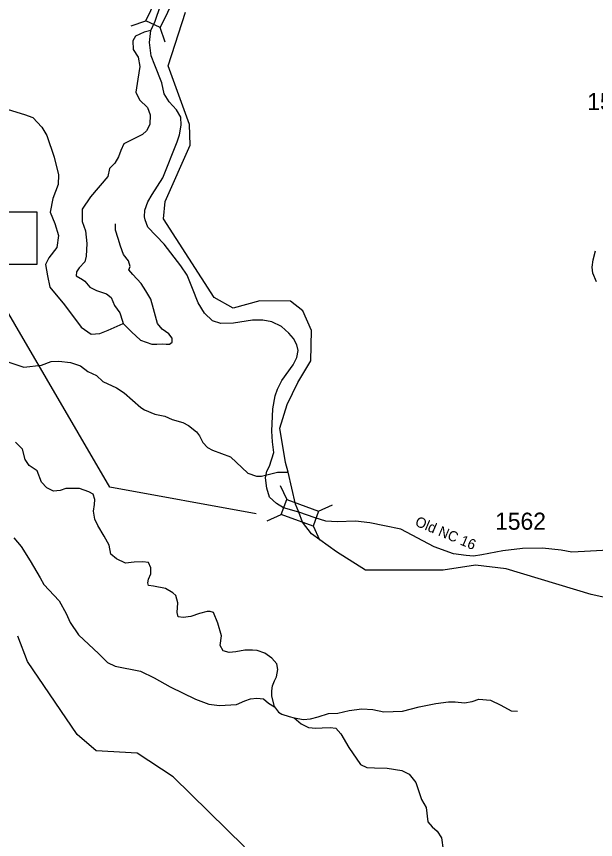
# Model space of a CAD drawing. Extents: x 1248224 to 1454986, y 825081 to 985870.
# Drawn here: x 1314642 to 1318874, y 928409 to 934427 of the extents above; entities that cross this region are included whole.
import ezdxf

# ---------------------------------------------------------------- set-up
doc = ezdxf.new("R2010")
doc.units = 0
for name, color, linetype in [('Exist Hydrographic Creek Single Shore', 7, 'Continuous'), ('Exist Hydrographic Misc Water Feature', 7, 'Continuous'), ('Exist Road Non-System Type 51', 7, 'Continuous'), ('Exist Road Secondary Structure Standard Bridge CELL', 7, 'Continuous'), ('Exist Road Secondary Structure Standard Bridge Number Label', 7, 'Continuous'), ('Exist Road Secondary Type 10 Attributed', 7, 'Continuous'), ('Exist Road Secondary Type 51 Attributed', 7, 'Continuous'), ('Exist Road Secondary Type 51 Label', 7, 'Continuous'), ('Exist Road Secondary Type 51 Number Label', 7, 'Continuous')]:
    doc.layers.add(name, color=color, linetype=linetype)

msp = doc.modelspace()

# ---------------------------------------------------------------- linework, layer by layer
at = {"layer": 'Exist Hydrographic Creek Single Shore'}
for points in [[(1316706.6, 930803.7), (1316682.2, 930860.1), (1316628.6, 931094.5), (1316608, 931166.9), (1316566.6, 931417.7), (1316620.9, 931591), (1316698.4, 931751.3), (1316792.5, 931908.1), (1316797.5, 932131.2), (1316734.5, 932273.6), (1316644.5, 932344.3), (1316419.5, 932348.9), (1316226.5, 932293.7), (1316086.5, 932372), (1315716.5, 932947.4), (1315727.5, 933075.2), (1315911.5, 933485.2), (1315907.5, 933636.2), (1315750.4, 934066.1), (1315878, 934458.4)], [(1316798.9, 930644.8), (1316732.9, 930729.2), (1316706.6, 930803.7)], [(1319185.3, 930124.2), (1318842.9, 930199.8), (1318220.7, 930388.5), (1317995.7, 930416.1), (1317761.4, 930379.3), (1317191.9, 930379.3), (1316980.6, 930512.7), (1316798.9, 930644.8)]]:
    msp.add_lwpolyline(points, dxfattribs=at)
at = {"layer": 'Exist Hydrographic Misc Water Feature'}
for points in [[(1314572, 931904.8), (1314695.1, 931862.1), (1314823.6, 931876.7), (1314896.1, 931903.2), (1314952.2, 931907.8), (1315036.2, 931897.9), (1315109.6, 931871.8), (1315162.7, 931830.6), (1315226, 931801.4), (1315273, 931758.6), (1315374, 931712.3), (1315429.3, 931675), (1315550.9, 931567.5), (1315578.5, 931551.4), (1315653.8, 931519.5), (1315725.6, 931505.8), (1315780.9, 931480), (1315858.5, 931458.8), (1315898, 931435.8), (1315957, 931390.3), (1315980.4, 931361.9), (1316003.2, 931313), (1316038.4, 931276.2), (1316074, 931255), (1316206.9, 931208), (1316332.2, 931087.4), (1316395.8, 931065.5), (1316431.8, 931064.8), (1316548.6, 931096.1), (1316628.6, 931094.5)], [(1316309.5, 928355.8), (1315787.5, 928868.5), (1315524.5, 929041.2), (1315224.5, 929057.1), (1315086.5, 929178), (1314723.4, 929710.6), (1314652.5, 929895.9)]]:
    msp.add_lwpolyline(points, dxfattribs=at)
at = {"layer": 'Exist Road Non-System Type 51'}
for points in [[(1315624.6, 934325.9), (1315575.2, 934313.3), (1315511.5, 934282.4), (1315493.1, 934249.5), (1315495.1, 934185.8), (1315532.1, 934130.3), (1315542.3, 934060.4), (1315528, 933970), (1315513.6, 933873.4), (1315540.3, 933817.9), (1315599.9, 933762.4), (1315618.3, 933706.9), (1315616.3, 933637), (1315591.6, 933591.8), (1315562.9, 933565.1), (1315427.3, 933495.2), (1315404.9, 933447.4), (1315388.4, 933400.1), (1315359.7, 933354.9), (1315322.7, 933315.9), (1315310.4, 933258.3), (1315183.1, 933108.3), (1315121.4, 933017.8), (1315121.4, 932927.4), (1315146.1, 932859.6), (1315156.4, 932767.1), (1315150.2, 932674.6), (1315142.1, 932634.3), (1315101, 932589.1), (1315080.5, 932560.3), (1315078.4, 932531.6), (1315125.6, 932504.8), (1315142.1, 932492.5), (1315177, 932447.3), (1315226.3, 932424.7), (1315300.2, 932398), (1315335.1, 932373.3), (1315357.7, 932313.7), (1315396.8, 932260.2), (1315417.3, 932198.6), (1315421.4, 932182.1)], [(1314581.2, 933746.1), (1314699.4, 933710.2), (1314760.3, 933688.7), (1314828.4, 933617), (1314864.2, 933556.1), (1314917.9, 933398.4), (1314950.2, 933269.3), (1314946.6, 933197.6), (1314907.2, 933097.2), (1314889.3, 932996.9), (1314921.5, 932914.4), (1314950.2, 932824.8), (1314935.8, 932738.8), (1314878.5, 932663.5), (1314853.5, 932613.3), (1314867.8, 932530.9), (1314885.7, 932448.4), (1314993.2, 932319.4), (1315114.9, 932154.5), (1315186.6, 932104.3), (1315251.1, 932107.9), (1315311.9, 932133), (1315421.4, 932182.1)], [(1315421.4, 932182.1), (1315483, 932120.5), (1315548.7, 932060.9), (1315630.9, 932032.1), (1315667.9, 932032.1), (1315708.9, 932034.2), (1315735.6, 932030), (1315761.4, 932030.9), (1315779.9, 932045.3), (1315779.9, 932076.1), (1315755.2, 932107), (1315705.9, 932139.8), (1315673.1, 932181), (1315644.3, 932289.9), (1315623.8, 932359.8), (1315586.8, 932421.4), (1315553.9, 932474.9), (1315492.8, 932541.6), (1315464.1, 932574.5), (1315472.3, 932599.2), (1315460, 932640.3), (1315423, 932687.5), (1315402.5, 932747.1), (1315386, 932804.7), (1315365.5, 932864.3), (1315365.5, 932911.6)], [(1316527.5, 929379.5), (1316509, 929459.6), (1316509, 929496.6), (1316513.1, 929531.6), (1316527.5, 929568.6), (1316541.9, 929599.4), (1316552.1, 929652.8), (1316543.9, 929693.9), (1316509, 929735), (1316457.6, 929772), (1316402.2, 929790.5), (1316367.3, 929794.6), (1316309.8, 929792.6), (1316246.1, 929780.3), (1316196.8, 929776.1), (1316153.7, 929788.5), (1316131.1, 929827.5), (1316139.3, 929897.4), (1316114.7, 929989.9), (1316081.8, 930070.1), (1316057.1, 930076.2), (1316034.6, 930076.2), (1315979.1, 930061.8), (1315915.4, 930039.2), (1315860, 930033.1), (1315823, 930037.2), (1315816.8, 930070.1), (1315821, 930139.9), (1315806.6, 930193.4), (1315784, 930213.9), (1315730.6, 930244.8), (1315642.9, 930262.3), (1315608, 930266.4), (1315601.8, 930287), (1315608, 930313.7), (1315624.4, 930352.8), (1315624.4, 930395.9), (1315608, 930435), (1315564.9, 930439.1), (1315501.2, 930437), (1315439.6, 930430.9), (1315371.8, 930461.7), (1315330.7, 930494.6), (1315320.5, 930560.4), (1315283.5, 930626.1), (1315236.2, 930706.3), (1315213.6, 930751.5), (1315205.5, 930810.1), (1315211.7, 930859.4), (1315213.8, 930894.3), (1315203.5, 930933.4), (1315170.6, 930951.9), (1315102.9, 930974.5), (1315002.2, 930974.5), (1314961.1, 930962.2), (1314911.8, 930956), (1314864.6, 930980.7), (1314825.6, 931021.8), (1314792.7, 931106), (1314735.2, 931143), (1314706.5, 931188.3), (1314685.9, 931264.3), (1314634.6, 931313.6)], [(1314623.2, 930615.6), (1314676.6, 930551.9), (1314742.3, 930447.1), (1314814.2, 930321.7), (1314843, 930274.4), (1314953.9, 930153.1), (1315005.2, 930062.7), (1315034, 929994.9), (1315095.6, 929906.5), (1315244.8, 929767.7), (1315306.4, 929704), (1315363.9, 929677.3), (1315548.7, 929640.3), (1315649.4, 929591), (1315764.4, 929525.2), (1315951.3, 929434.8), (1316047.8, 929397.8), (1316125.9, 929389.5), (1316249.1, 929395.7), (1316309.8, 929422.6), (1316352.9, 929437), (1316398.1, 929443.2), (1316447.4, 929437), (1316484.3, 929406.2), (1316527.5, 929379.5)], [(1316670.7, 929299.9), (1316740.5, 929285.5), (1316791.9, 929291.7), (1316847.3, 929306.1), (1316921.3, 929330.7), (1316991.1, 929332.8), (1317073.3, 929353.4), (1317165.7, 929363.6), (1317245.8, 929359.5), (1317327.9, 929343.1), (1317463.5, 929347.2), (1317584.7, 929378), (1317705.8, 929404.7), (1317798.3, 929415), (1317847.6, 929415), (1317916.4, 929408.9), (1317971.9, 929417.1), (1318021.2, 929435.6), (1318105.4, 929427.4), (1318181.4, 929392.4), (1318257.4, 929349.3), (1318304.6, 929347.2)], [(1316527.5, 929379.5), (1316557.7, 929341), (1316580.3, 929324.6), (1316633.7, 929308.1), (1316670.7, 929299.9)], [(1316670.7, 929299.9), (1316723.3, 929255.4), (1316776.7, 929228.7), (1316830.1, 929222.6), (1316877.3, 929226.7), (1316934.8, 929228.7), (1316975.9, 929222.6), (1317012.9, 929181.4), (1317070.4, 929082.8), (1317156.7, 928957.4), (1317201.8, 928934.8), (1317259.3, 928932.7), (1317351.8, 928930.7), (1317458.6, 928914.2), (1317512, 928887.5), (1317561.3, 928825.9), (1317602.3, 928700.5), (1317635.2, 928642.9), (1317647.5, 928538.1), (1317680.4, 928501.1), (1317717.4, 928470.3), (1317748.2, 928421), (1317760.5, 928332.6)]]:
    msp.add_lwpolyline(points, dxfattribs=at)
at = {"layer": 'Exist Road Secondary Structure Standard Bridge CELL'}
for p, q in [((1315481.1, 934358.9), (1315587.9, 934396.3)), ((1315729.7, 934239.3), (1315692.3, 934346.1)), ((1316569.1, 930998.1), (1316616.7, 930895.4)), ((1316849.2, 930809.4), (1316951.9, 930856.9)), ((1316474, 930739.2), (1316576.7, 930786.7)), ((1316810.1, 930703.2), (1316857.7, 930600.5))]:
    msp.add_line(p, q, dxfattribs=at)
for points in [[(1315587.9, 934396.3), (1315695.4, 934619.7), (1315799.8, 934569.5), (1315692.3, 934346.1)], [(1316616.7, 930895.4), (1316849.3, 930809.9), (1316809.4, 930701.2), (1316576.7, 930786.7)]]:
    msp.add_lwpolyline(points, close=True, dxfattribs=at)
at = {"layer": 'Exist Road Secondary Structure Standard Bridge Number Label'}
msp.add_lwpolyline([(1313861.3, 932997.9), (1314790.2, 932997.9), (1314790.2, 932613.8), (1313861.3, 932613.8)], close=True, dxfattribs=at)
msp.add_lwpolyline([(1316394.7, 930790.4), (1315324.5, 930986.6), (1314397.1, 932573.9)], dxfattribs=at)
at = {"layer": 'Exist Road Secondary Type 10 Attributed'}
msp.add_lwpolyline([(1318881.3, 932487.4), (1318854, 932551.3), (1318849.4, 932595.2), (1318856.3, 932648.5), (1318874.9, 932713.3)], dxfattribs=at)
at = {"layer": 'Exist Road Secondary Type 51 Attributed'}
for points in [[(1316706.6, 930803.7), (1316593.3, 930834.3), (1316541.4, 930866), (1316491.2, 930911.8), (1316471.6, 930977.2), (1316462.9, 931053.6), (1316471.6, 931101.5), (1316491.2, 931138.6), (1316521.8, 931239), (1316513, 931317.5), (1316508.7, 931393.8), (1316515, 931558.5), (1316532.5, 931654.4), (1316549.9, 931702.4), (1316580.4, 931765.7), (1316663.2, 931879.1), (1316691.6, 931933.6), (1316700.3, 931983.8), (1316691.6, 932027.4), (1316667.6, 932073.2), (1316632.7, 932112.5), (1316578.9, 932159.3), (1316509.2, 932194.2), (1316441.6, 932207.3), (1316367.5, 932207.3), (1316228, 932185.5), (1316136.5, 932181.1), (1316075.4, 932200.8), (1316016.6, 932257.5), (1315970.8, 932333.8), (1315927.2, 932438.5), (1315890.2, 932534.5), (1315842.2, 932604.3), (1315720.8, 932762.8), (1315600.9, 932887.1), (1315581.3, 932939.5), (1315576.9, 932961.3), (1315579.1, 933011.4), (1315600.9, 933072.5), (1315633.6, 933124.9), (1315711.6, 933248), (1315816.2, 933509.8), (1315833.7, 933562.1), (1315844.6, 933631.9), (1315842.4, 933690.8), (1315811.9, 933745.3), (1315757.4, 933802.1), (1315722.5, 933860.9), (1315705.1, 933941.7), (1315652.9, 934070.7), (1315626.8, 934138.3), (1315613.7, 934236.5), (1315624.6, 934325.9), (1315655.1, 934393.5), (1315695.4, 934507.7)], [(1319182, 930491.9), (1319139.3, 930516.3), (1319071.8, 930533.7), (1319023.8, 930535.9), (1318925.7, 930522.8), (1318792.8, 930514.1), (1318701.3, 930509.7), (1318622.8, 930525), (1318486.5, 930540.3), (1318340.5, 930535.9), (1318196.7, 930520.6), (1318044.1, 930490.1), (1317983.1, 930481.4), (1317928.6, 930485.7), (1317834.9, 930498.8), (1317694, 930548.5), (1317449.9, 930677.2), (1317332.2, 930703.4), (1317225.4, 930725.2), (1317120.7, 930736.1), (1316985.6, 930731.7), (1316902.8, 930736.1), (1316824.3, 930760.1), (1316706.6, 930803.7)]]:
    msp.add_lwpolyline(points, dxfattribs=at)

# ---------------------------------------------------------------- texts
at = {"layer": 'Exist Road Secondary Type 51 Label'}
msp.add_text('Old NC 16', height=75, rotation=337.18137, dxfattribs=at).set_placement((1317548.9, 930706.2))
at = {"layer": 'Exist Road Secondary Type 51 Number Label'}
for s, p in [('1563', (1318813.5, 933742.7)), ('1562', (1318140, 930674.1))]:
    msp.add_text(s, height=125, dxfattribs=at).set_placement(p)

doc.saveas('drawing.dxf')
